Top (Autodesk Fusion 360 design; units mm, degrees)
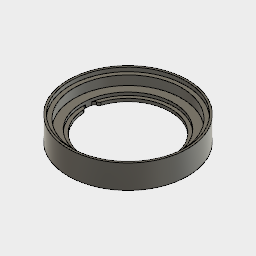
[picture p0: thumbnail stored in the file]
parameter "height" = 20 comment "height of the component"
parameter "rail_height" = 4
parameter "exrtusion_delta_for_magnets" = 0.8
parameter "diameter" = 120
parameter "inner_diameter" = 108
parameter "diameter_offet" = 3
parameter "pressfit_offset" = 1
parameter "magnet_diameter" = 6.4
parameter "magnet_height" = 3.2
parameter "holes_position_from_diameter" = 20
parameter "plateform_height" = 3
parameter "plateform_inner_diameter" = 85
parameter "magnet_offset" = 1.6 (= "diameter - holes_position_from_diameter - matrix_diameter - magnet_diameter")
parameter "matrix_diameter" = 92
parameter "matrix_height" = 3
sketch "base" plane through (0, 0, 0) normal (0, 1, 0) x axis (1, 0, 0)
  circle C1 centre (0, 0) radius 60
  circle C2 centre (0, 0) radius 54
  dimension "d1" diameter C1 = 120 (= "diameter")
  dimension "d63" diameter C2 = 108 (= "inner_diameter")
sketch "arround magnets" plane through (0, 0, 0) normal (0, 1, 0) x axis (1, 0, 0)
  circle C1 centre (0, 50) radius 4
  point P1 (0, 0)
  point P2 (0, 50)
  dimension "d124" diameter C1 = 8 (= "magnet_diameter + magnet_offset")
  dimension "d130" distance P1 P2 = 50 (= "diameter / 2 - holes_position_from_diameter / 2")
extrude "Extrude18" new body sketch "arround magnets" along normal blind 10.8 (= "rail_height + plateform_height + exrtusion_delta_for_magnets + matrix_height")
circular_pattern "C-Pattern6" TotalAngle 360
extrude "Extrude8" new body sketch "base" along normal blind 20 (= "height")
combine "Combine2"
sketch "top_holes" plane through (0, 20, 0) normal (0, 1, 0) x axis (-1, 0, 0)
  circle C1 centre (0, 50) radius 3.2
  circle C2 centre (-43.3013, -25) radius 3.2
  circle C3 centre (43.3013, -25) radius 3.2
  point P1 (0, 0)
  point P4 (43.3013, -25)
  dimension "d5" diameter C1 = 6.4 (= "magnet_diameter")
  dimension "d94" distance P1 P4 = 50 (= "diameter / 2 - holes_position_from_diameter / 2")
  dimension "d7" C-Pattern1-Angle = 360
sketch "top_rail_out" plane through (0, 20, 0) normal (0, 1, 0) x axis (-1, 0, 0)
  circle C1 centre (0, 0) radius 60
  circle C2 centre (0, 0) radius 58
  circle C3 centre (0, 0) radius 60
  circle C4 centre (0, 0) radius 54
  dimension "d65" diameter C2 = 116 (= "diameter - diameter_offet - pressfit_offset")
  dimension "d96" diameter C1 = 120 (= "diameter")
extrude "Extrude10" add sketch "top_rail_out" profile of C1 C2 along normal blind 4 (= "rail_height")
sketch "bottom_holes" plane through (0, 0, 0) normal (0, -1, 0) x axis (1, 0, 0)
  circle C1 centre (-43.3013, -25) radius 3.2
  point P1 (0, 0)
  point P2 (-43.3013, -25)
  dimension "d57" diameter C1 = 6.4 (= "magnet_diameter")
  dimension "d95" distance P1 P2 = 50 (= "diameter / 2 - holes_position_from_diameter / 2")
work_plane "WorkPlane1" AlongDistance 0
work_point "WorkPoint1"
work_axis "WorkAxis1"
sketch "bottom_rail_out" plane through (0, 0, 0) normal (0, -1, 0) x axis (1, 0, 0)
  circle C1 centre (0, 0) radius 55
  circle C2 centre (0, 0) radius 60
  arc A1 centre (0, 0) radius 54 clockwise from (0, -54) to (-46.7654, -27)
  arc A2 centre (0, 0) radius 54 clockwise from (-46.7654, -27) to (-46.7654, 27)
  arc A3 centre (0, 0) radius 54 clockwise from (-46.7654, 27) to (0, 54)
  arc A4 centre (0, 0) radius 54 clockwise from (0, 54) to (46.7654, 27)
  arc A5 centre (0, 0) radius 54 clockwise from (46.7654, 27) to (46.7654, -27)
  arc A6 centre (0, 0) radius 54 clockwise from (46.7654, -27) to (0, -54)
  dimension "d67" diameter C1 = 110 (= "diameter - diameter_offet - 7 mm")
sketch "Sketch19" plane through (0, 0, 0) normal (0, 1, 0) x axis (1, 0, 0)
  circle C1 centre (0, 0) radius 42.5
  circle C2 centre (0, 0) radius 54
  dimension "d132" diameter C1 = 85 (= "plateform_inner_diameter")
  dimension "d134" diameter C2 = 108 (= "inner_diameter")
extrude "Extrude14" cut sketch "bottom_holes" no distance stored
circular_pattern "C-Pattern1" TotalAngle 360
extrude "Extrude15" cut sketch "bottom_rail_out" profile of C1 against normal blind 4.8 (magnitude of "-1 * rail_height - exrtusion_delta_for_magnets")
extrude "Extrude19" sketch "Sketch19" blind 3 (= "plateform_height")
fillet "Fillet3" radius 3
sketch "plateform" plane through (0, 7.8, 0) normal (0, 1, 0) x axis (-1, 0, 0)
  arc A1 centre (-43.7339, 17.2146) radius 3 clockwise from (-46.5255, 18.3134) to (-44.2989, 20.1609)
  arc A2 centre (0, 0) radius 50 clockwise from (-46.5255, -18.3134) to (-46.5255, 18.3134)
  arc A3 centre (-43.7339, -17.2146) radius 3 clockwise from (-44.2989, -20.1609) to (-46.5255, -18.3134)
  arc A4 centre (-45.4663, -26.25) radius 6.2 clockwise from (-44.2989, -20.1609) to (-39.6093, -28.2835)
  arc A5 centre (-36.7752, -29.2674) radius 3 clockwise from (-39.1226, -31.1356) to (-39.6093, -28.2835)
  arc A6 centre (0, 0) radius 50 clockwise from (-7.4029, -49.4489) to (-39.1226, -31.1356)
  arc A7 centre (-6.9587, -46.482) radius 3 clockwise from (-4.6896, -48.4444) to (-7.4029, -49.4489)
  arc A8 centre (0, -52.5) radius 6.2 clockwise from (-4.6896, -48.4444) to (4.6896, -48.4444)
  arc A9 centre (6.9587, -46.482) radius 3 clockwise from (7.4029, -49.4489) to (4.6896, -48.4444)
  arc A10 centre (0, 0) radius 50 clockwise from (39.1226, -31.1356) to (7.4029, -49.4489)
  arc A11 centre (36.7752, -29.2674) radius 3 clockwise from (39.6093, -28.2835) to (39.1226, -31.1356)
  arc A12 centre (45.4663, -26.25) radius 6.2 clockwise from (39.6093, -28.2835) to (44.2989, -20.1609)
  arc A13 centre (43.7339, -17.2146) radius 3 clockwise from (46.5255, -18.3134) to (44.2989, -20.1609)
  arc A14 centre (0, 0) radius 50 clockwise from (46.5255, 18.3134) to (46.5255, -18.3134)
  arc A15 centre (43.7339, 17.2146) radius 3 clockwise from (44.2989, 20.1609) to (46.5255, 18.3134)
  arc A16 centre (45.4663, 26.25) radius 6.2 clockwise from (44.2989, 20.1609) to (39.6093, 28.2835)
  arc A17 centre (36.7752, 29.2674) radius 3 clockwise from (39.1226, 31.1356) to (39.6093, 28.2835)
  arc A18 centre (0, 0) radius 50 clockwise from (7.4029, 49.4489) to (39.1226, 31.1356)
  arc A19 centre (6.9587, 46.482) radius 3 clockwise from (4.6896, 48.4444) to (7.4029, 49.4489)
  arc A20 centre (0, 52.5) radius 6.2 clockwise from (4.6896, 48.4444) to (-4.6896, 48.4444)
  arc A21 centre (-6.9587, 46.482) radius 3 clockwise from (-7.4029, 49.4489) to (-4.6896, 48.4444)
  arc A22 centre (0, 0) radius 50 clockwise from (-39.1226, 31.1356) to (-7.4029, 49.4489)
  arc A23 centre (-36.7752, 29.2674) radius 3 clockwise from (-39.6093, 28.2835) to (-39.1226, 31.1356)
  arc A24 centre (-45.4663, 26.25) radius 6.2 clockwise from (-39.6093, 28.2835) to (-44.2989, 20.1609)
  circle C1 centre (0, 0) radius 42.5
  circle C2 centre (0, 0) radius 46
  circle C3 centre (0, 0) radius 42.5
  arc A25 centre (0, 0) radius 54 clockwise from (46.7654, 27) to (46.7654, -27)
  circle C4 centre (43.3013, 25) radius 4
  arc A26 centre (0, 0) radius 54 clockwise from (0, 54) to (46.7654, 27)
  circle C5 centre (0, 50) radius 4
  arc A27 centre (0, 0) radius 54 clockwise from (-46.7654, 27) to (0, 54)
  circle C6 centre (-43.3013, 25) radius 4
  arc A28 centre (0, 0) radius 54 clockwise from (-46.7654, -27) to (-46.7654, 27)
  circle C7 centre (-43.3013, -25) radius 4
  arc A29 centre (0, 0) radius 54 clockwise from (0, -54) to (-46.7654, -27)
  circle C8 centre (0, -50) radius 4
  arc A30 centre (0, 0) radius 54 clockwise from (46.7654, -27) to (0, -54)
  circle C9 centre (43.3013, -25) radius 4
  dimension "d151" diameter C2 = 92 (= "matrix_diameter")
extrude "Extrude23" cut of existing geometry blind 3.2 (= "magnet_height")
sketch "Sketch27" plane through (0, 7.8, 0) normal (0, 1, 0) x axis (-1, 0, 0)
  arc A1 centre (0, 0) radius 54 clockwise from (46.7654, 27) to (46.7654, -27)
  circle C1 centre (43.3013, 25) radius 4
  arc A2 centre (0, 0) radius 54 clockwise from (0, 54) to (46.7654, 27)
  circle C2 centre (0, 50) radius 4
  arc A3 centre (0, 0) radius 54 clockwise from (-46.7654, 27) to (0, 54)
  circle C3 centre (-43.3013, 25) radius 4
  arc A4 centre (0, 0) radius 54 clockwise from (-46.7654, -27) to (-46.7654, 27)
  circle C4 centre (-43.3013, -25) radius 4
  arc A5 centre (0, 0) radius 54 clockwise from (0, -54) to (-46.7654, -27)
  circle C5 centre (0, -50) radius 4
  arc A6 centre (0, 0) radius 54 clockwise from (46.7654, -27) to (0, -54)
  circle C6 centre (43.3013, -25) radius 4
  circle C7 centre (0, 0) radius 42.5
  circle C8 centre (0, 0) radius 54
  circle C9 centre (0, 0) radius 46
  dimension "d157" diameter C8 = 108 (= "inner_diameter")
  dimension "d158" diameter C9 = 92 (= "matrix_diameter")
extrude "Extrude24" add sketch "Sketch27" along normal blind 3 (= "matrix_height")
sketch "hole_for_cables" plane through (0, 7.8, 0) normal (0, 1, 0) x axis (-1, 0, 0)
  line L1 (46, 0.0302) -> (0, 0)
  line L2 (44.4326, -11.9057) -> (0, 0)
  line L3 (46, 0) -> (0, 0)
  line L4 (41.0518, -10.9998) -> (44.4326, -11.9057)
  line L5 (46, 0) -> (42.5, 0)
  line L6 (46, 0.0302) -> (42.5, 0)
  line L7 (44.4326, -11.9057) -> (41.0518, -10.9998)
  circle C1 centre (0, 0) radius 46
  circle C2 centre (0, 0) radius 42.5
  point P3 (0, 0)
  point P4 (46, 0.0302)
  point P5 (44.4326, -11.9057)
  dimension "d161" distance P3 P4 = 46 (= "matrix_diameter / 2")
  dimension "d162" angle L2 L3 = 15
  dimension "d163" distance P3 P5 = 46 (= "matrix_diameter / 2")
extrude "Extrude25" cut sketch "hole_for_cables" profile of C1 C2 L1 L2 no distance stored
fillet "Fillet4" radius 3
named bodies: "Part A Top"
